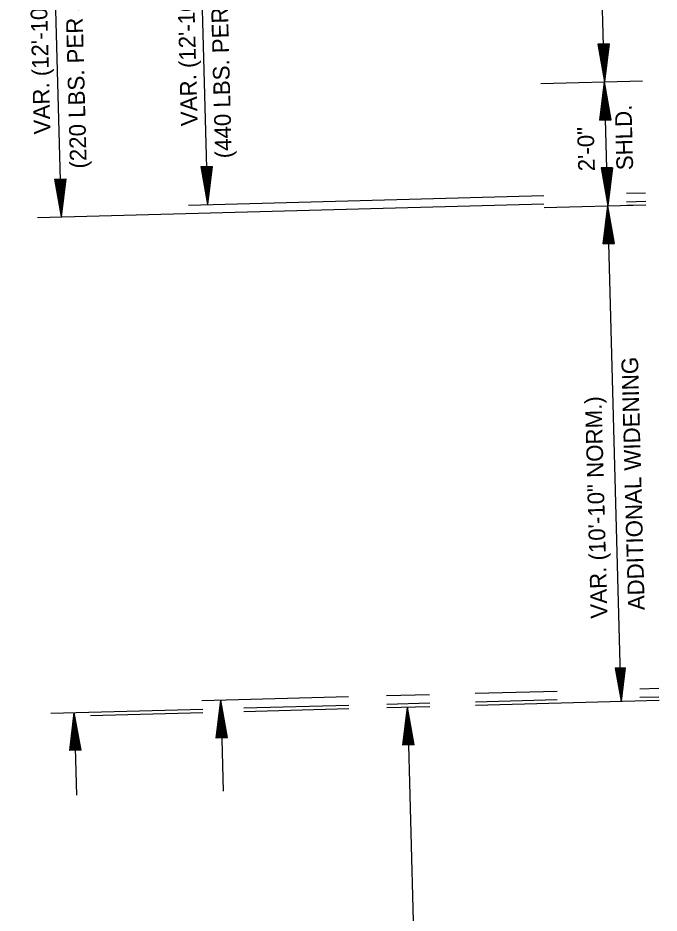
# Model space of a CAD drawing. Extents: x 1926836 to 1933254, y 596317 to 604524.
# Drawn here: x 1932770.4 to 1933001.4, y 596572.3 to 596895 of the extents above; entities that cross this region are included whole.
import ezdxf

# ---------------------------------------------------------------- set-up
doc = ezdxf.new("R2010")
doc.units = 0
doc.layers.add('Default', color=7, linetype='Continuous')

msp = doc.modelspace()

# ---------------------------------------------------------------- linework, layer by layer
at = {"layer": 'Default'}
for p, q in [((1932777.54, 597135.41), (1932785.92, 596823.27)), ((1932830.48, 597133.34), (1932838.69, 596827.76)), ((1932981.66, 596871.93), (1932979.25, 596961.83)), ((1932983.35, 596885.68), (1932979.26, 596885.57)), ((1932979.26, 596885.57), (1932981.66, 596871.93)), ((1932979.58, 596885.58), (1932981.6, 596874.21)), ((1932979.94, 596885.59), (1932981.54, 596876.56)), ((1932980.27, 596885.6), (1932981.48, 596878.85)), ((1932980.64, 596885.61), (1932981.41, 596881.16)), ((1932980.97, 596885.62), (1932981.35, 596883.43)), ((1932981.62, 596885.64), (1932981.35, 596883.43)), ((1932981.98, 596885.65), (1932981.41, 596881.16)), ((1932982.31, 596885.66), (1932981.48, 596878.85)), ((1932982.67, 596885.67), (1932981.54, 596876.56)), ((1932983.01, 596885.67), (1932981.6, 596874.21)), ((1932983.35, 596885.68), (1932981.66, 596871.93)), ((1932958.72, 596871.32), (1932995.36, 596872.3)), ((1932979.99, 596858.2), (1932981.66, 596871.93)), ((1932982.86, 596827.28), (1932981.66, 596871.93)), ((1932984.09, 596858.31), (1932981.66, 596871.93)), ((1932980.32, 596858.21), (1932981.72, 596869.64)), ((1932983.75, 596858.3), (1932981.72, 596869.64)), ((1932980.68, 596858.22), (1932981.79, 596867.31)), ((1932983.41, 596858.3), (1932981.79, 596867.31)), ((1932981.01, 596858.23), (1932981.85, 596865.04)), ((1932981.38, 596858.24), (1932981.91, 596862.68)), ((1932983.05, 596858.29), (1932981.85, 596865.04)), ((1932982.72, 596858.28), (1932981.91, 596862.68)), ((1932981.71, 596858.25), (1932981.97, 596860.41)), ((1932982.36, 596858.27), (1932981.97, 596860.41)), ((1932979.99, 596858.2), (1932984.09, 596858.31)), ((1932836.28, 596841.4), (1932840.38, 596841.51)), ((1932836.28, 596841.4), (1932838.69, 596827.76)), ((1932836.61, 596841.41), (1932838.62, 596830.07)), ((1932836.97, 596841.42), (1932838.56, 596832.4)), ((1932837.29, 596841.43), (1932838.5, 596834.68)), ((1932837.67, 596841.44), (1932838.44, 596837)), ((1932838, 596841.44), (1932838.38, 596839.28)), ((1932838.63, 596841.46), (1932838.38, 596839.28)), ((1932839.01, 596841.47), (1932838.44, 596837)), ((1932839.35, 596841.48), (1932838.5, 596834.68)), ((1932839.69, 596841.49), (1932838.56, 596832.4)), ((1932840.04, 596841.5), (1932838.62, 596830.07)), ((1932840.38, 596841.51), (1932838.69, 596827.76)), ((1932984.55, 596841.03), (1932980.45, 596840.92)), ((1932980.45, 596840.92), (1932982.86, 596827.28)), ((1932980.78, 596840.93), (1932982.8, 596829.56)), ((1932981.14, 596840.94), (1932982.74, 596831.91)), ((1932981.47, 596840.94), (1932982.67, 596834.19)), ((1932981.84, 596840.95), (1932982.61, 596836.5)), ((1932982.17, 596840.96), (1932982.55, 596838.77)), ((1932982.82, 596840.98), (1932982.55, 596838.77)), ((1932983.18, 596840.99), (1932982.61, 596836.5)), ((1932983.51, 596841), (1932982.67, 596834.19)), ((1932983.87, 596841.01), (1932982.74, 596831.91)), ((1932984.21, 596841.02), (1932982.8, 596829.56)), ((1932984.55, 596841.03), (1932982.86, 596827.28)), ((1932783.51, 596836.91), (1932787.61, 596837.02)), ((1932783.51, 596836.91), (1932785.92, 596823.27)), ((1932783.84, 596836.92), (1932785.86, 596825.54)), ((1932784.19, 596836.93), (1932785.79, 596827.91)), ((1932784.52, 596836.94), (1932785.73, 596830.19)), ((1932784.91, 596836.95), (1932785.67, 596832.51)), ((1932785.22, 596836.96), (1932785.61, 596834.78)), ((1932785.88, 596836.97), (1932785.61, 596834.78)), ((1932786.23, 596836.98), (1932785.67, 596832.51)), ((1932786.56, 596836.99), (1932785.73, 596830.19)), ((1932786.92, 596837), (1932785.79, 596827.91)), ((1932787.26, 596837.01), (1932785.86, 596825.54)), ((1932787.61, 596837.02), (1932785.92, 596823.27)), ((1932831.85, 596827.57), (1932959.8, 596831.01)), ((1932989.58, 596831.81), (1932996.44, 596831.99)), ((1932777.41, 596823.04), (1932959.88, 596827.94)), ((1932959.92, 596826.66), (1932996.56, 596827.64)), ((1932981.19, 596813.55), (1932982.86, 596827.28)), ((1932987.66, 596648.65), (1932982.86, 596827.28)), ((1932985.29, 596813.66), (1932982.86, 596827.28)), ((1932989.66, 596828.74), (1932996.52, 596828.92)), ((1932989.7, 596827.46), (1932996.56, 596827.64)), ((1932981.52, 596813.56), (1932982.92, 596824.99)), ((1932984.95, 596813.65), (1932982.92, 596824.99)), ((1932981.88, 596813.57), (1932982.98, 596822.65)), ((1932982.21, 596813.57), (1932983.05, 596820.38)), ((1932984.61, 596813.64), (1932982.98, 596822.65)), ((1932984.25, 596813.63), (1932983.05, 596820.38)), ((1932982.58, 596813.58), (1932983.11, 596818.02)), ((1932983.92, 596813.62), (1932983.11, 596818.02)), ((1932981.19, 596813.55), (1932985.29, 596813.66)), ((1932982.91, 596813.59), (1932983.17, 596815.75)), ((1932983.56, 596813.61), (1932983.17, 596815.75)), ((1932989.13, 596660.7), (1932985.53, 596660.6)), ((1932985.53, 596660.6), (1932987.66, 596648.65)), ((1932985.83, 596660.61), (1932987.6, 596650.65)), ((1932986.14, 596660.62), (1932987.55, 596652.72)), ((1932986.44, 596660.62), (1932987.49, 596654.72)), ((1932986.74, 596660.63), (1932987.44, 596656.75)), ((1932987.05, 596660.64), (1932987.38, 596658.75)), ((1932987.61, 596660.65), (1932987.38, 596658.75)), ((1932987.91, 596660.66), (1932987.44, 596656.75)), ((1932988.22, 596660.67), (1932987.49, 596654.72)), ((1932988.52, 596660.68), (1932987.55, 596652.72)), ((1932988.83, 596660.69), (1932987.6, 596650.65)), ((1932989.13, 596660.7), (1932987.66, 596648.65)), ((1932935.1, 596651.57), (1932964.6, 596652.36)), ((1932994.38, 596653.16), (1933001.23, 596653.35)), ((1932836.64, 596648.93), (1932889.48, 596650.35)), ((1932841.81, 596635.38), (1932843.48, 596649.11)), ((1932843.48, 596649.11), (1932844.36, 596616.2)), ((1932845.91, 596635.49), (1932843.48, 596649.11)), ((1932903.16, 596650.71), (1932918.67, 596651.13)), ((1932935.18, 596648.5), (1932964.68, 596649.3)), ((1932935.21, 596647.24), (1933001.35, 596649.02)), ((1932994.46, 596650.09), (1933001.32, 596650.28)), ((1932782.21, 596644.4), (1932837.01, 596645.87)), ((1932842.14, 596635.39), (1932843.54, 596646.85)), ((1932845.57, 596635.48), (1932843.54, 596646.85)), ((1932851.77, 596646.26), (1932889.57, 596647.28)), ((1932851.8, 596645), (1932889.6, 596646.02)), ((1932903.24, 596647.65), (1932918.76, 596648.06)), ((1932903.28, 596646.39), (1932918.79, 596646.8)), ((1932909.03, 596632.84), (1932910.7, 596646.59)), ((1932910.7, 596646.59), (1932918.18, 596368.04)), ((1932913.13, 596632.95), (1932910.7, 596646.59)), ((1932789.04, 596630.9), (1932790.71, 596644.63)), ((1932793.14, 596631.01), (1932790.71, 596644.63)), ((1932790.71, 596644.63), (1932791.51, 596614.79)), ((1932796.52, 596643.52), (1932837.04, 596644.61)), ((1932842.5, 596635.4), (1932843.61, 596644.5)), ((1932845.22, 596635.47), (1932843.61, 596644.5)), ((1932909.36, 596632.84), (1932910.76, 596644.32)), ((1932912.79, 596632.94), (1932910.76, 596644.32)), ((1932789.37, 596630.9), (1932790.77, 596642.36)), ((1932789.72, 596630.91), (1932790.84, 596640)), ((1932792.79, 596631), (1932790.77, 596642.36)), ((1932792.45, 596630.99), (1932790.84, 596640)), ((1932842.82, 596635.41), (1932843.67, 596642.24)), ((1932843.2, 596635.42), (1932843.73, 596639.91)), ((1932844.88, 596635.47), (1932843.67, 596642.24)), ((1932844.54, 596635.46), (1932843.73, 596639.91)), ((1932909.72, 596632.85), (1932910.83, 596641.95)), ((1932910.05, 596632.86), (1932910.89, 596639.66)), ((1932912.45, 596632.93), (1932910.83, 596641.95)), ((1932912.09, 596632.92), (1932910.89, 596639.66)), ((1932790.05, 596630.92), (1932790.9, 596637.71)), ((1932792.09, 596630.98), (1932790.9, 596637.71)), ((1932843.53, 596635.43), (1932843.79, 596637.62)), ((1932844.16, 596635.45), (1932843.79, 596637.62)), ((1932910.42, 596632.87), (1932910.95, 596637.35)), ((1932911.76, 596632.91), (1932910.95, 596637.35)), ((1932790.44, 596630.93), (1932790.96, 596635.39)), ((1932790.75, 596630.94), (1932791.02, 596633.12)), ((1932791.76, 596630.97), (1932790.96, 596635.39)), ((1932791.41, 596630.96), (1932791.02, 596633.12)), ((1932845.91, 596635.49), (1932841.81, 596635.38)), ((1932913.13, 596632.95), (1932909.03, 596632.84)), ((1932910.75, 596632.88), (1932911.01, 596635.07)), ((1932911.4, 596632.9), (1932911.01, 596635.07)), ((1932793.14, 596631.01), (1932789.04, 596630.9))]:
    msp.add_line(p, q, dxfattribs=at)

# ---------------------------------------------------------------- texts
for s, p in [('VAR. (12\'-10" NORM.) ACHM SURFACE COURSE (1/2")', (1932782.15, 596853.12)), ('VAR. (12\'-10" NORM.) ACHM BINDER COURSE (1")', (1932835.15, 596856.09)), ('(440 LBS. PER SQ. YD.) & TACK COAT', (1932847.47, 596844.49)), ('(220 LBS. PER SQ. YD.) & TACK COAT', (1932795.19, 596840.8)), ('SHLD.', (1932992.03, 596840.2)), ('2\'-0"', (1932978.24, 596839.83)), ('ADDITIONAL WIDENING', (1932996.2, 596681.55)), ('VAR. (10\'-10" NORM.)', (1932982.77, 596678.54))]:
    msp.add_text(s, height=6, rotation=91.5377, dxfattribs=at).set_placement(p)

doc.saveas('drawing.dxf')
